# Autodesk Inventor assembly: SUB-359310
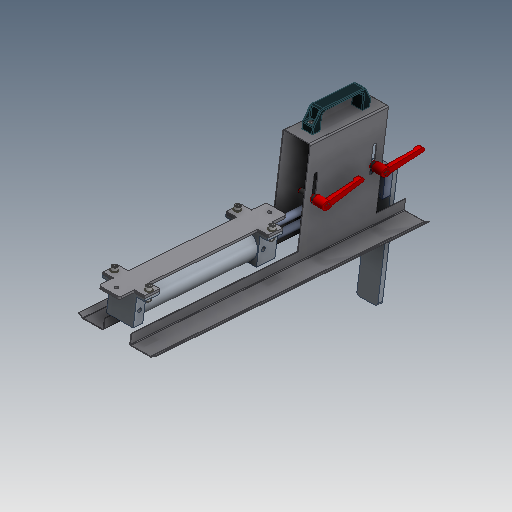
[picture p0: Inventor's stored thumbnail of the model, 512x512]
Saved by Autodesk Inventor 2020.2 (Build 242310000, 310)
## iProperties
Created: 2000-01
Part Number: SUB-359310
Document SubType Name: Assembly
Designer: cmcgourin
Mass: 7601.27 g
Surface Area: 7421.59 cm^2
Volume: 2137.43 cm^3
Density: 3.55627 g/cm^3
Control State: 0
Checked Out: False
Master: False
Shininess: 0.0
Length Units: 11269
Angle Units: 11279
Time Units: 11290
Mass Units: 11283
Length Display Precision: 3
Angle Display Precision: 2
Compacted: True
Dimensions: 511,8x762,3x218,6 mm
Mass: 7,601 kg
DocNumber: SUB-359310.iam
Folder: 01 - Themengebiete\Simplification\01 - Packaging machine\
VDS_Category: 3D Komponenten
Density: 0.0
Volumn: 0.0
Area: 0.0
PropertySet Name: Model Information
Author: cmcgourin
Revision Number: -
Title: SUB-359310
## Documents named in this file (12)
- D:\07 - DEMODATEN\OTX 2019 - Dataset - UPDATE - Dez2019\Designs\07-Packing machine\SUB-359310.iam
- D:\07 - DEMODATEN\OTX 2019 - Dataset - UPDATE - Dez2019\Designs\07-Packing machine\A105181.iam
- D:\07 - DEMODATEN\OTX 2019 - Dataset - UPDATE - Dez2019\Designs\07-Packing machine\Parts\ADSK-011488.ipt
- D:\07 - DEMODATEN\OTX 2019 - Dataset - UPDATE - Dez2019\Designs\07-Packing machine\Parts\ADSK-011493.ipt
- D:\07 - DEMODATEN\OTX 2019 - Dataset - UPDATE - Dez2019\Designs\07-Packing machine\Parts\ADSK-011774.ipt
- D:\07 - DEMODATEN\OTX 2019 - Dataset - UPDATE - Dez2019\Designs\07-Packing machine\Parts\ADSK-011555.ipt
- D:\07 - DEMODATEN\OTX 2019 - Dataset - UPDATE - Dez2019\Content Center Files\de-DE\ISO 4762(2)\ISO 4762 - M6 x 20ISO.ipt
- D:\07 - DEMODATEN\OTX 2019 - Dataset - UPDATE - Dez2019\Content Center Files\de-DE\ISO 4762(2)\ISO 4762 - M8 x 20ISO.ipt
- D:\07 - DEMODATEN\OTX 2019 - Dataset - UPDATE - Dez2019\Content Center Files\de-DE\DIN 125-1  B\DIN 125-1 - B 8,4.ipt
- D:\07 - DEMODATEN\OTX 2019 - Dataset - UPDATE - Dez2019\Content Center Files\de-DE\ISO 4032(1)\ISO 4032 - M8DIN EN.ipt
- D:\07 - DEMODATEN\OTX 2019 - Dataset - UPDATE - Dez2019\Libraries\PURCHASED PARTS\Ganter\Griffe\Adjustable hand lever GN 300-78-M10-32-RS.ipt
- D:\07 - DEMODATEN\OTX 2019 - Dataset - UPDATE - Dez2019\Content Center Files\de-DE\ISO 4762(2)\ISO 4762 - M8 x 25ISO.ipt
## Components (34 placed, 11 different names)
1. A105181 [sub-assembly] — Passend:14, Passend:15, Passend:16, Passend:17, Passend:18, Fluchtend:18, POSITION, Passend:23
2. ADSK-011488:1 — Passend:14, Passend:15, Passend:23
3. ADSK-011493:2 — Fluchtend:15, Passend:16, Passend:17, Passend:18
4. ADSK-011555:1 — POSITION, Fluchtend:15, Fluchtend:18, Passend:20, Passend:21, Passend:22, Passend:24, Passend:25, Passend:26, Passend:27, Passend:28, Passend:29
5. ADSK-011774:1 — Passend:20, Passend:21, Passend:22
6. Adjustable hand lever GN 300-78-M10-32-RS:1 — Passend:24, Passend:28
7. Adjustable hand lever GN 300-78-M10-32-RS:2 — Passend:26, Passend:27
8. Adjustable hand lever GN 300-78-M10-32-RS:3 — Passend:25, Passend:29
9. ISO 4762 M6 x 20:1
10. ISO 4762 M6 x 20:2
11. ISO 4762 M6 x 20:3
12. ISO 4762 M6 x 20:4
13. ISO 4762 M8 x 20:1
14. ISO 4762 M8 x 20:2
15. DIN 125-1 B B 8,4:1
16. DIN 125-1 B B 8,4:2
17. DIN EN 24032 M8:1
18. DIN EN 24032 M8:2
19. DIN 125-1 B B 8,4:3
20. DIN 125-1 B B 8,4:4
21. DIN 125-1 B B 8,4:5
22. DIN 125-1 B B 8,4:6
23. DIN EN 24032 M8:3
24. DIN EN 24032 M8:4
25. DIN EN 24032 M8:5
26. DIN EN 24032 M8:6
27. DIN 125-1 B B 8,4:7
28. DIN 125-1 B B 8,4:8
29. DIN 125-1 B B 8,4:9 — Passend:31, Passend:33, Passend:35, Passend:37
30. DIN 125-1 B B 8,4:10
31. ISO 4762 M8 x 25:1 — Passend:31
32. ISO 4762 M8 x 25:2 — Passend:33
33. ISO 4762 M8 x 25:3 — Passend:35
34. ISO 4762 M8 x 25:4 — Passend:37
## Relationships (22: Mate 20, Flush 2)
- POSITION [Mate]: A105181 ↔ ADSK-011555:1
- Fluchtend:15 [Flush]: ADSK-011493:2 ↔ ADSK-011555:1
- Passend:14 [Mate]: A105181 ↔ ADSK-011488:1
- Passend:15 [Mate]: A105181 ↔ ADSK-011488:1
- Passend:16 [Mate]: A105181 ↔ ADSK-011493:2
- Passend:17 [Mate]: A105181 ↔ ADSK-011493:2
- Passend:18 [Mate]: A105181 ↔ ADSK-011493:2
- Fluchtend:18 [Flush]: A105181 ↔ ADSK-011555:1
- Passend:20 [Mate]: ADSK-011555:1 ↔ ADSK-011774:1
- Passend:21 [Mate]: ADSK-011555:1 ↔ ADSK-011774:1
- Passend:22 [Mate]: ADSK-011555:1 ↔ ADSK-011774:1
- Passend:23 [Mate]: A105181 ↔ ADSK-011488:1
- Passend:24 [Mate]: ADSK-011555:1 ↔ Adjustable hand lever GN 300-78-M10-32-RS:1
- Passend:25 [Mate]: ADSK-011555:1 ↔ Adjustable hand lever GN 300-78-M10-32-RS:3
- Passend:26 [Mate]: ADSK-011555:1 ↔ Adjustable hand lever GN 300-78-M10-32-RS:2
- Passend:27 [Mate]: ADSK-011555:1 ↔ Adjustable hand lever GN 300-78-M10-32-RS:2
- Passend:28 [Mate]: ADSK-011555:1 ↔ Adjustable hand lever GN 300-78-M10-32-RS:1
- Passend:29 [Mate]: ADSK-011555:1 ↔ Adjustable hand lever GN 300-78-M10-32-RS:3
- Passend:31 [Mate]: DIN 125-1 B B 8,4:9 ↔ ISO 4762 M8 x 25:1
- Passend:33 [Mate]: DIN 125-1 B B 8,4:9 ↔ ISO 4762 M8 x 25:2
- Passend:35 [Mate]: DIN 125-1 B B 8,4:9 ↔ ISO 4762 M8 x 25:3
- Passend:37 [Mate]: DIN 125-1 B B 8,4:9 ↔ ISO 4762 M8 x 25:4
